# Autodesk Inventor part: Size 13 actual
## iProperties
Created: 2006-11
Part Number: Size 13 actual
Document SubType Name: Modeling
Designer: Andrew DuBuc
Density: 1 g/cm^3
Author: Andrew DuBuc
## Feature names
1. Revolution1
